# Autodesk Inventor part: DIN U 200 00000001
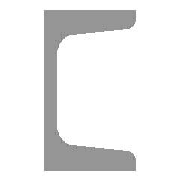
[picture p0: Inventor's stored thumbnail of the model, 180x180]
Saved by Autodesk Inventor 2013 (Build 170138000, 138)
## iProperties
IsCustomPart: 1
Created: 2009-11
Part Number: DIN U 200 00000001
Material: Steel, Mild
Description: U-Shape
Document SubType Name: Modeling
Standard: DIN
Designer: pokornp
Standard Revision: 2000
Standards Organization: DIN
Language: en-US
Size Designation: U 200
Categories: <MemberInstance><Categories><Category DisplayName="Structural Shapes" InternalName="089c4875-fa83-4c05-b084-43b9cc11f5ed" Mnemonic="GRDR"><CategoryParameter Dis
Stock Number: U 200
Density: 7.86 g/cm^3
_CCFamilyMember: 15
_CCFamilyDisplayName: DIN 1026 U - U-Shape
_FrameMemberDoc: Frame Member File
_Version: 15.0.0
G_L: 2500.000 mm
G_W: 75.000 mm
G_H: 200.000 mm
Author: pokornp
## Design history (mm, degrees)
node "Start plane"
node "End plane"
sketch "Sketch"
  geometry: L1 (0, 0)-(0, 100); L2 (0, 100)-(75, 100); L3 (75, 100)-(75, 97.039); L4 (69.478, 91.058)-(19.083, 87.027); L5 (8.5, 75.563)-(8.5, 0); L6 (8.5, 0)-(0, 0); L7 (37.5, 100)-(37.5, 88.5); L8 (75, 91.5)-(75, 88.5); L9 (75, 88.5)-(37.5, 88.5); L10 (0, 15)-(0, -27); L11 (-5.539, 0)-(16.007, 0); L12 (0, 0)-(0, -100); L13 (0, -100)-(75, -100); L14 (75, -100)-(75, -97.039); L15 (69.478, -91.058)-(19.083, -87.027); L16 (8.5, -75.563)-(8.5, 0); L17 (0, 140)-(0, -140) reference; L18 (-21.881, 0)-(92.511, 0) reference; A1 r 11.5 centre (20, 75.563) between (19.083, 87.027) and (8.5, 75.563); A2 r 11.5 centre (20, -75.563) between (8.5, -75.563) and (19.083, -87.027); A3 r 6 centre (69, 97.039) between (69.478, 91.058) and (75, 97.039); A4 r 6 centre (69, -97.039) between (75, -97.039) and (69.478, -91.058); 5 further points
  constraints: 32 end point, 10 point on line, 8 point on circle, 8 tangent, 6 symmetric about line, 4 centre point, 4 parallel, 3 collinear, 3 perpendicular, 2 equal radius, 2 midpoint, 5 other
  dimensions: "d0" = 8.5 distance between parallel lines of L1 L5 (= G_T); "d1" = 100 distance between parallel lines of L6 L2 (= 0.5 x G_H); "d2" = 75 distance between parallel lines of L3 L1 (= G_W); "d3" = 11.5 distance of L2.end L8.end (= G_T1); "d4" = 37.5 distance of L7.start L2.end (= G_C); "d5" = 3 distance of L8.start L8.end (computed from G_NG, G_C); "d23" = 11.5 radius of A1 (= G_IR); "d24" = 6 radius of A3 (= G_ER); "d25" = 0 distance between parallel lines of L10 L12 (computed from ex)
extrude "Body" new body sketch "Sketch" stored distance "d6" = 2500 (= G_L); taper "d7" = 0 deg
node "Driven Length"
  sketch "Sketch3"
    geometry: L1 (0, 0)-(10, 0) reference
    constraints: 2 end point, 1 horizontal
  workplane "Work Plane3"
  sketch "Sketch4"
    geometry: L1 (-2, 0)-(12, 0) reference; L2 (-2, 2500)-(12, 2500) reference
    dimensions: "d29" = 2500 distance between parallel lines of L1 L2 (derived)
body "Solid1"
other parameters: "G_W" = 75 [user parameter; used in 1 equation term], "G_H" = 200 [user parameter; used in 1 equation term], "G_T" = 8.5 [user parameter; used in 1 equation term], "G_T1" = 11.5 [user parameter; used in 1 equation term], "G_NG" = 0.8 [user parameter; used in 1 equation term], "G_ER" = 6 [user parameter; used in 1 equation term], "G_IR" = 11.5 [user parameter; used in 1 equation term], "G_C" = 37.5 [user parameter; used in 2 equation terms], "G_L" = 2500 (= d29) [user parameter; used in 1 equation term], "ex" = 0 [user parameter; used in 1 equation term], "G_OFFSET_START" = 0 [user parameter; used in 1 equation term], "G_OFFSET_END" = 0 [user parameter; used in 1 equation term], "d26" = 0 (computed from G_OFFSET_START), "d28" = 90 deg
